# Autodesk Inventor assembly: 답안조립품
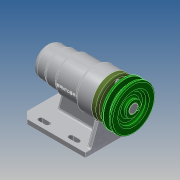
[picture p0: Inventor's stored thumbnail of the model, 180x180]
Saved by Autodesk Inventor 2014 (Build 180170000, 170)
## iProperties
Created: 2017-09
Part Number: 답안조립품
Document SubType Name: Assembly
Designer: kb542-15
Author: kb542-15
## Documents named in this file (12)
- C:\Users\kb542-15\Desktop\470907V1022\답안조립품.iam
- C:\Users\kb542-15\Desktop\470907V1022\1-본체.ipt
- C:\Users\kb542-15\Desktop\470907V1022\베어링 6004.ipt
- C:\Users\kb542-15\Desktop\470907V1022\베어링 51202.ipt
- C:\Users\kb542-15\Desktop\470907V1022\어댑터슬리브.ipt
- C:\Users\kb542-15\Desktop\470907V1022\오일 실 20x35x7.ipt
- C:\Users\kb542-15\Desktop\470907V1022\축.ipt
- C:\Users\kb542-15\Desktop\470907V1022\커버.ipt
- C:\Users\kb542-15\Desktop\470907V1022\키 5 x 5 x 16.ipt
- C:\Users\kb542-15\Desktop\470907V1022\볼트 M4 x 12.ipt
- C:\Users\kb542-15\Desktop\470907V1022\V벨트풀리.ipt
- C:\Users\kb542-15\Desktop\470907V1022\멈춤나사 M3x8.ipt
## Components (2 placed, 2 different names)
1. 1-본체:1
2. V벨트풀리:1
